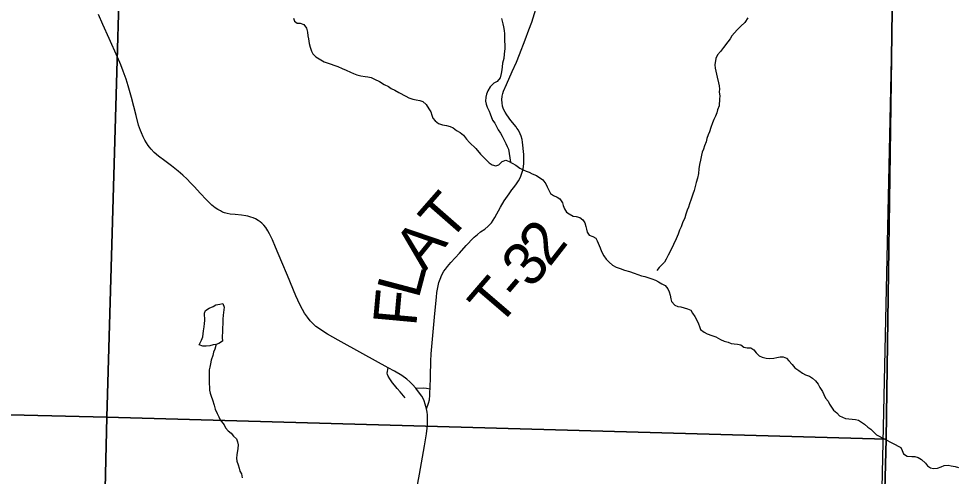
# Model space of a CAD drawing. Extents: x -7.9 to 76.1, y 0 to 22.
# Drawn here: x 4.221 to 5.448, y 15.305 to 15.904 of the extents above; entities that cross this region are included whole.
import ezdxf

# ---------------------------------------------------------------- set-up
doc = ezdxf.new("R2010")
doc.units = 0
for name, color, linetype in [('DV_X_Township_Line', 7, 'Continuous'), ('GM_X_Minor_River', 7, 'Continuous'), ('GM_X_Section', 7, 'Continuous'), ('GM_X_State_Route', 7, 'Continuous'), ('GM_X_Township_Road', 7, 'Continuous'), ('GM_X_Township_Road_Text', 7, 'Continuous')]:
    doc.layers.add(name, color=color, linetype=linetype)

msp = doc.modelspace()

# ---------------------------------------------------------------- linework, layer by layer
at = {"layer": 'DV_X_Township_Line'}
msp.add_lwpolyline([(5.3187, 14.1), (5.3187, 14.1), (5.3308, 14.5457), (5.3468, 15.1527), (5.3492, 15.2488), (5.3496, 15.269), (5.3835, 16.8368), (5.4044, 17.6173), (5.4237, 18.2356), (4.9631, 18.2309), (4.7878, 18.2356), (4.712, 18.2376), (4.641, 18.2398), (3.9131, 18.2522), (2.8136, 18.2741), (2.7747, 18.2739), (2.7625, 18.2742), (2.7582, 18.2743), (2.1, 18.2862)], dxfattribs=at)
at = {"layer": 'GM_X_Minor_River'}
for points in [[(4.5805, 15.9044), (4.5817, 15.9006), (4.5855, 15.8981), (4.5893, 15.8981), (4.5938, 15.8963), (4.5977, 15.8914), (4.5986, 15.8862)], [(4.8525, 15.9043), (4.8542, 15.8971), (4.855, 15.8933), (4.8558, 15.8884), (4.8563, 15.8842), (4.8564, 15.8793), (4.8566, 15.8649), (4.856, 15.8573), (4.8553, 15.852), (4.8539, 15.8455), (4.8533, 15.8409), (4.8529, 15.8368), (4.8519, 15.8322), (4.8505, 15.8265), (4.8468, 15.8219), (4.8426, 15.8195), (4.8378, 15.8149), (4.8345, 15.8095), (4.8327, 15.805), (4.832, 15.8011), (4.8317, 15.7958), (4.8325, 15.7921), (4.8337, 15.7883), (4.8361, 15.783), (4.8377, 15.7793), (4.8408, 15.771), (4.8436, 15.7672), (4.8455, 15.7635), (4.8482, 15.7586), (4.851, 15.7541), (4.8533, 15.7503), (4.8557, 15.7458), (4.858, 15.7406), (4.86, 15.7368), (4.8616, 15.733), (4.8644, 15.7161)], [(5.1745, 15.905), (5.1705, 15.8988), (5.1653, 15.8942), (5.1604, 15.8892), (5.1571, 15.8853), (5.1534, 15.8815), (5.1512, 15.8776), (5.1482, 15.8734), (5.1427, 15.8661), (5.1386, 15.8611), (5.1349, 15.8565), (5.1327, 15.8519), (5.1313, 15.8436), (5.1318, 15.839), (5.1334, 15.8315), (5.1346, 15.8273), (5.1363, 15.8201), (5.1371, 15.816), (5.1376, 15.8118), (5.1372, 15.808), (5.1377, 15.8027), (5.1374, 15.7989), (5.1368, 15.7898), (5.135, 15.7845), (5.1339, 15.7807), (5.1321, 15.7765), (5.1299, 15.7719), (5.1285, 15.7677), (5.1263, 15.7616), (5.1245, 15.7559), (5.1227, 15.7517), (5.1209, 15.7471), (5.1198, 15.7425), (5.1177, 15.7375), (5.1166, 15.7333), (5.1148, 15.7291), (5.1141, 15.7253), (5.1127, 15.7185), (5.1113, 15.7132), (5.1106, 15.7075), (5.11, 15.7014), (5.1086, 15.6953), (5.1071, 15.6896), (5.1054, 15.6827), (5.1043, 15.6789), (5.1025, 15.674), (5.1003, 15.6675), (5.0982, 15.6614), (5.0967, 15.6572), (5.0953, 15.6534), (5.0935, 15.648), (5.0921, 15.6431), (5.0891, 15.6369), (5.0873, 15.6316), (5.0851, 15.627), (5.0833, 15.6217), (5.0808, 15.6156), (5.0771, 15.6083), (5.0746, 15.6026), (5.0702, 15.5942), (5.0676, 15.5892), (5.0654, 15.5854), (5.0621, 15.5815), (5.0584, 15.5784), (5.0554, 15.5742)], [(4.5986, 15.8862), (4.5994, 15.8816), (4.6002, 15.8775), (4.6011, 15.8714), (4.6023, 15.8665), (4.6039, 15.8616), (4.6059, 15.8578), (4.6097, 15.8541), (4.6162, 15.8501), (4.6208, 15.8475), (4.6284, 15.8446), (4.6345, 15.8428), (4.6383, 15.8414), (4.644, 15.8388), (4.6494, 15.8366), (4.6551, 15.8341), (4.6589, 15.8322), (4.6635, 15.8304), (4.6684, 15.829), (4.6741, 15.8283), (4.6779, 15.8276), (4.6821, 15.827), (4.6863, 15.8248), (4.6928, 15.8215), (4.6989, 15.8178), (4.7046, 15.8152), (4.7084, 15.8126), (4.713, 15.8104), (4.7184, 15.8075), (4.7275, 15.8023), (4.7314, 15.8001), (4.7363, 15.7987), (4.7409, 15.7977), (4.7458, 15.797), (4.7496, 15.7955), (4.7538, 15.7914), (4.7573, 15.7858), (4.7601, 15.7821), (4.7613, 15.7775), (4.7628, 15.7738), (4.7656, 15.77), (4.7702, 15.7667), (4.7751, 15.7649), (4.7804, 15.7642), (4.7854, 15.7628), (4.7892, 15.761), (4.7938, 15.7576), (4.7984, 15.7551), (4.8026, 15.7513), (4.8068, 15.7461), (4.8107, 15.742), (4.8188, 15.7342), (4.825, 15.7267), (4.8292, 15.7222), (4.8327, 15.7185), (4.8365, 15.7152), (4.8403, 15.7126), (4.8449, 15.7111), (4.849, 15.7127), (4.8535, 15.717), (4.858, 15.7186), (4.8626, 15.7171), (4.8664, 15.7149), (4.871, 15.712), (4.8764, 15.7083), (4.8806, 15.7061), (4.8848, 15.7043), (4.8886, 15.7032), (4.8924, 15.701), (4.8981, 15.6988), (4.9065, 15.6929), (4.9104, 15.6876), (4.912, 15.6839), (4.9143, 15.6794), (4.9167, 15.6752), (4.9205, 15.6723), (4.9251, 15.6701), (4.9289, 15.6679), (4.932, 15.663), (4.9332, 15.6592), (4.9348, 15.6551), (4.9372, 15.6506), (4.941, 15.6484), (4.946, 15.6454), (4.9501, 15.6451), (4.9547, 15.6437), (4.9589, 15.6407), (4.9616, 15.6366), (4.9628, 15.6321), (4.9637, 15.6283), (4.9645, 15.6245), (4.9672, 15.6204), (4.9718, 15.619), (4.9756, 15.6168), (4.9775, 15.613), (4.9815, 15.604), (4.9831, 15.5991), (4.9862, 15.5934), (4.9893, 15.5893), (4.9932, 15.5852), (4.9974, 15.5811)], [(4.9974, 15.5811), (5.0024, 15.5786), (5.0077, 15.5768), (5.0134, 15.5746), (5.0199, 15.5728), (5.026, 15.5706), (5.0355, 15.5674), (5.0397, 15.5663), (5.0488, 15.5635), (5.0537, 15.5616), (5.0579, 15.5594), (5.0621, 15.5569), (5.0663, 15.5547), (5.0698, 15.5502), (5.0718, 15.5464), (5.073, 15.5419), (5.0738, 15.5374), (5.0747, 15.5336), (5.0789, 15.5287), (5.0831, 15.5273), (5.0869, 15.5266), (5.0914, 15.5255), (5.0956, 15.5241), (5.0998, 15.5223), (5.1022, 15.5185), (5.1053, 15.514), (5.1076, 15.5091), (5.11, 15.5046), (5.1112, 15.5009), (5.1127, 15.4971), (5.1174, 15.4934), (5.1212, 15.4912), (5.1273, 15.4894), (5.1326, 15.4876), (5.1387, 15.4839), (5.1437, 15.4817), (5.1486, 15.4803), (5.1528, 15.4788), (5.1566, 15.4785), (5.1608, 15.4778), (5.1653, 15.4772), (5.1692, 15.4738), (5.1737, 15.4731), (5.1783, 15.4729), (5.1825, 15.4706), (5.1852, 15.4665), (5.1894, 15.4628), (5.1932, 15.461), (5.1985, 15.4596), (5.2031, 15.4593), (5.2084, 15.4594), (5.2125, 15.4602), (5.2167, 15.4614), (5.2205, 15.4615), (5.225, 15.4596), (5.2281, 15.4559), (5.2324, 15.4514), (5.2358, 15.4469), (5.2412, 15.4432), (5.2458, 15.4399), (5.25, 15.4377), (5.255, 15.4359), (5.2592, 15.4333), (5.263, 15.43), (5.2665, 15.4255), (5.2688, 15.421), (5.2723, 15.4157), (5.2739, 15.412), (5.2759, 15.4071), (5.2794, 15.4034), (5.2813, 15.3992), (5.2837, 15.3955), (5.2864, 15.3913), (5.291, 15.388), (5.2945, 15.3839), (5.2983, 15.3821), (5.3021, 15.3806), (5.3066, 15.38), (5.3153, 15.3793), (5.3191, 15.3783), (5.323, 15.3757), (5.3272, 15.3731), (5.3314, 15.3694), (5.3352, 15.3664), (5.3391, 15.3627), (5.3426, 15.359)], [(4.4573, 15.4769), (4.4603, 15.483), (4.4621, 15.4876), (4.4627, 15.4955), (4.4637, 15.5005), (4.464, 15.5051), (4.4644, 15.5088), (4.4642, 15.5183), (4.4656, 15.5221), (4.4701, 15.5249), (4.4754, 15.5272), (4.4791, 15.5292), (4.4844, 15.5304), (4.4882, 15.5313), (4.4898, 15.5264), (4.4888, 15.5195), (4.4884, 15.5157), (4.4882, 15.5108), (4.4883, 15.5047), (4.4876, 15.499), (4.4877, 15.4952), (4.4871, 15.4865), (4.4875, 15.482), (4.483, 15.4788), (4.4793, 15.4776), (4.4755, 15.4768), (4.471, 15.4756), (4.4664, 15.4751), (4.4619, 15.4754), (4.4573, 15.4769)], [(4.4796, 15.4777), (4.4775, 15.4715), (4.4757, 15.4673), (4.475, 15.4632), (4.4728, 15.4571), (4.4721, 15.4521), (4.4711, 15.4479), (4.4704, 15.4441), (4.4701, 15.44), (4.4703, 15.4259), (4.4708, 15.4214), (4.4709, 15.4176), (4.4717, 15.4138), (4.4729, 15.4097), (4.4745, 15.4052), (4.4769, 15.398), (4.4781, 15.3927), (4.4808, 15.3871), (4.4828, 15.3826), (4.4848, 15.3788), (4.4898, 15.3721), (4.4918, 15.3683), (4.4952, 15.3646), (4.4991, 15.3612), (4.5022, 15.3575), (4.506, 15.3538), (4.5072, 15.35), (4.508, 15.3462), (4.5077, 15.3413), (4.5064, 15.3329), (4.5061, 15.3288), (4.5065, 15.3246), (4.5081, 15.3201), (4.5093, 15.3155), (4.5105, 15.3118), (4.5125, 15.308), (4.5133, 15.3031)], [(5.3426, 15.359), (5.3745, 15.3426), (5.3761, 15.3388), (5.3781, 15.3343), (5.383, 15.3313), (5.3887, 15.331), (5.3929, 15.3307), (5.3971, 15.3296), (5.4017, 15.327), (5.4067, 15.3221), (5.4094, 15.3184), (5.4132, 15.3158), (5.4174, 15.3151), (5.4223, 15.3155), (5.4272, 15.3175), (5.4313, 15.3191), (5.4363, 15.3195), (5.4401, 15.3188), (5.4454, 15.3177), (5.45, 15.3163)]]:
    msp.add_lwpolyline(points, dxfattribs=at)
at = {"layer": 'GM_X_Section'}
for points in [[(3.3491, 16.4191), (4.3656, 16.3922), (4.3363, 15.3822), (3.3274, 15.4069)], [(5.3702, 16.3705), (5.3678, 16.2579), (5.3554, 15.3537), (4.3363, 15.3822), (4.3656, 16.3922)], [(6.2227, 16.2415), (6.1958, 15.241), (5.3532, 15.2703), (5.3554, 15.3537), (5.3678, 16.2579)], [(4.3363, 15.3822), (4.313, 14.3761), (3.3054, 14.3948), (3.3274, 15.4069)], [(4.3363, 15.3822), (5.3554, 15.3537), (5.3532, 15.2703), (5.3252, 14.3506), (4.313, 14.3761)]]:
    msp.add_lwpolyline(points, close=True, dxfattribs=at)
at = {"layer": 'GM_X_State_Route'}
msp.add_lwpolyline([(4.7389, 15.2725), (4.7454, 15.3079), (4.7518, 15.3446), (4.7544, 15.3604), (4.7554, 15.3679), (4.7558, 15.3737), (4.7555, 15.3855), (4.7552, 15.389), (4.7544, 15.3932), (4.7527, 15.3995), (4.7512, 15.4039), (4.7499, 15.4066), (4.7481, 15.4098), (4.744, 15.4156), (4.7403, 15.4204), (4.7362, 15.425), (4.7325, 15.4287), (4.7288, 15.4319), (4.7221, 15.4369), (4.7127, 15.4424), (4.7041, 15.4471), (4.6711, 15.4653), (4.639, 15.483), (4.6248, 15.4911), (4.6161, 15.4966), (4.6131, 15.4987), (4.6099, 15.5012), (4.608, 15.5028), (4.6056, 15.5051), (4.6025, 15.5083), (4.5988, 15.513), (4.5951, 15.5183), (4.5921, 15.5234), (4.589, 15.5298), (4.5837, 15.541), (4.5726, 15.5677), (4.5654, 15.5852), (4.557, 15.6048), (4.5529, 15.6145), (4.5505, 15.6196), (4.5492, 15.6222), (4.5471, 15.6263), (4.5443, 15.6306), (4.5418, 15.6338), (4.5392, 15.6362), (4.5369, 15.6379), (4.5341, 15.6398), (4.5307, 15.6418), (4.5279, 15.6431), (4.5247, 15.6443), (4.5209, 15.6453), (4.5183, 15.6458), (4.5126, 15.6466), (4.5041, 15.6474), (4.4977, 15.6482), (4.4938, 15.6488), (4.4903, 15.6497), (4.4875, 15.6508), (4.4849, 15.6522), (4.4815, 15.654), (4.4779, 15.6565), (4.4737, 15.6598), (4.4666, 15.667), (4.4585, 15.6757), (4.451, 15.6838), (4.446, 15.6889), (4.4413, 15.6937), (4.4358, 15.6989), (4.4298, 15.7043), (4.4209, 15.7113), (4.4122, 15.7177), (4.4042, 15.7238), (4.3984, 15.7287), (4.3943, 15.7331), (4.3923, 15.7356), (4.3904, 15.7381), (4.3882, 15.7415), (4.3861, 15.7451), (4.3838, 15.7494), (4.3816, 15.7544), (4.3804, 15.7574), (4.378, 15.7647), (4.3747, 15.7771), (4.3686, 15.8009), (4.3645, 15.8159), (4.3616, 15.8248), (4.3578, 15.8353), (4.3546, 15.8434), (4.3503, 15.8537), (4.3397, 15.878), (4.3312, 15.8965), (4.3254, 15.9094)], dxfattribs=at)
at = {"layer": 'GM_X_Township_Road'}
for points in [[(4.7544, 15.3932), (4.7569, 15.4006), (4.7581, 15.4052), (4.7586, 15.4109), (4.7589, 15.4161), (4.759, 15.4196), (4.7595, 15.4361), (4.7601, 15.4558), (4.7604, 15.4651), (4.7629, 15.4941), (4.7652, 15.518), (4.7673, 15.5395), (4.7679, 15.5454), (4.7695, 15.5542), (4.7707, 15.5586), (4.7723, 15.5631), (4.7746, 15.5687), (4.7772, 15.5734), (4.7791, 15.5761), (4.7817, 15.5796), (4.7864, 15.5848), (4.7974, 15.597), (4.8062, 15.6069), (4.8087, 15.6098), (4.8132, 15.6146), (4.8168, 15.618), (4.821, 15.6215), (4.8251, 15.6247), (4.8306, 15.6286), (4.8352, 15.6324), (4.8392, 15.6368), (4.8415, 15.6401), (4.8436, 15.6438), (4.8513, 15.6573), (4.8561, 15.6654), (4.8623, 15.6748), (4.8658, 15.6797), (4.8686, 15.683), (4.872, 15.6877), (4.8747, 15.6918), (4.8771, 15.6964), (4.8791, 15.7017), (4.8799, 15.7045), (4.8806, 15.7075), (4.8815, 15.714), (4.8817, 15.7192), (4.8815, 15.7261), (4.8801, 15.7424), (4.8794, 15.7457), (4.8782, 15.75), (4.8768, 15.7534), (4.8746, 15.7578), (4.8727, 15.7608), (4.8714, 15.7625), (4.8648, 15.7707), (4.8595, 15.7781), (4.8572, 15.7815), (4.855, 15.7856), (4.8538, 15.7896), (4.8532, 15.7936), (4.853, 15.7978), (4.8534, 15.8025), (4.8542, 15.8059), (4.8552, 15.8089), (4.8589, 15.8178), (4.8664, 15.8346), (4.8719, 15.8471), (4.8759, 15.857), (4.8834, 15.8762), (4.8882, 15.8891), (4.8919, 15.8995), (4.8992, 15.9221)], [(4.7264, 15.4077), (4.7199, 15.4153), (4.7159, 15.4199), (4.7125, 15.424), (4.7098, 15.4272), (4.7066, 15.4323), (4.7043, 15.4361), (4.7033, 15.4383), (4.703, 15.4397), (4.7041, 15.4471)], [(4.7403, 15.4204), (4.75, 15.4205), (4.7545, 15.4202), (4.759, 15.4196)]]:
    msp.add_lwpolyline(points, dxfattribs=at)

# ---------------------------------------------------------------- texts
at = {"layer": 'GM_X_Township_Road_Text'}
for s, rotation, p in [('T', 48.7967, (4.7831, 15.6097)), ('2', 52.1626, (4.9151, 15.5777)), ('A', 50.8987, (4.7519, 15.5713)), ('3', 50.1824, (4.8914, 15.5492)), ('L', 75.1561, (4.7439, 15.5359)), ('T', 49.3466, (4.848, 15.4985)), ('-', 49.5009, (4.8758, 15.5309)), ('F', 84.7853, (4.7409, 15.5002))]:
    msp.add_text(s, height=0.0568, rotation=rotation, dxfattribs=at).set_placement(p)

doc.saveas('drawing.dxf')
